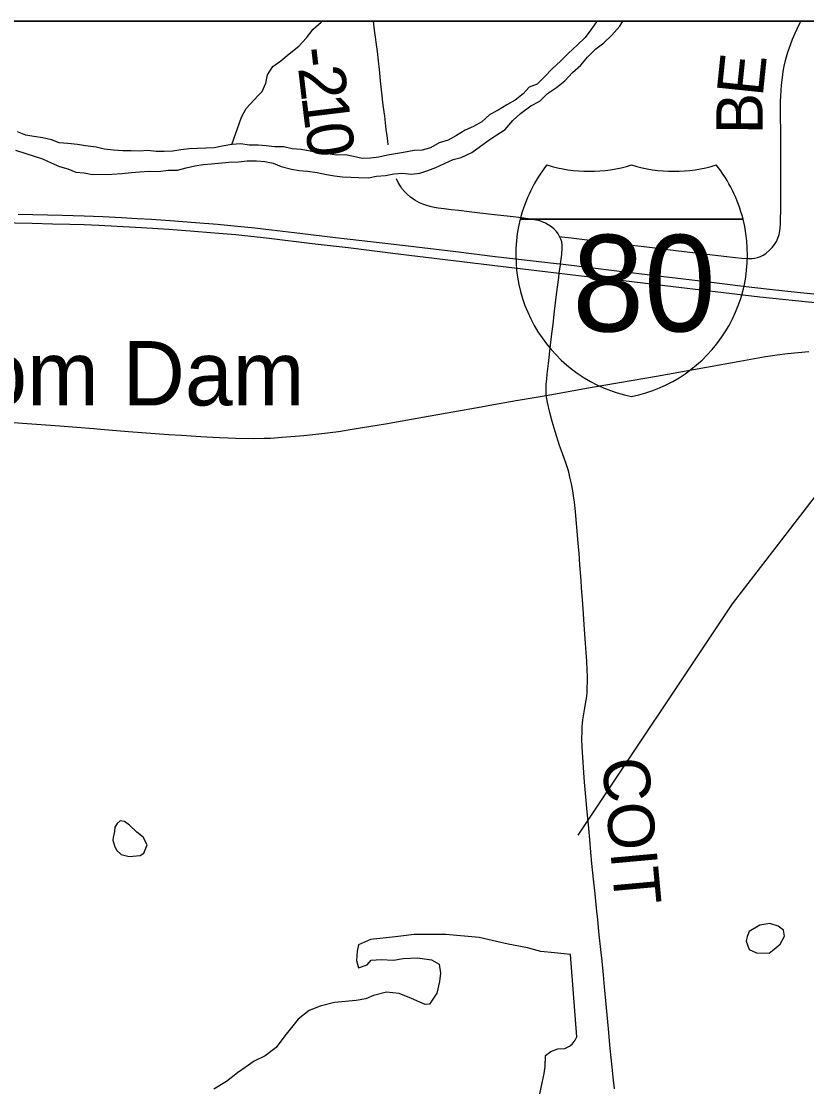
# Model space of a CAD drawing. Extents: x 0 to 34, y 0 to 22.
# Drawn here: x 6.131 to 7.094, y 19.311 to 20.617 of the extents above; entities that cross this region are included whole.
import ezdxf

# ---------------------------------------------------------------- set-up
doc = ezdxf.new("R2010")
doc.units = 0
for name, color, linetype in [('GM_X_Corporation', 7, 'Continuous'), ('GM_X_County_Road', 7, 'Continuous'), ('GM_X_County_Road_Text', 7, 'Continuous'), ('GM_X_Interstate_Location', 7, 'Continuous'), ('GM_X_Interstate_Route', 7, 'Continuous'), ('GM_X_Interstate_Shield', 7, 'Continuous'), ('GM_X_Major_River', 7, 'Continuous'), ('GM_X_Minor_Lake', 7, 'Continuous'), ('GM_X_Minor_River', 7, 'Continuous'), ('GM_X_State_Route', 7, 'Continuous'), ('GM_X_Township_Road', 7, 'Continuous'), ('GM_X_Township_Road_Text', 7, 'Continuous'), ('GM_X_Unincorporated_Text', 7, 'Continuous'), ('SH_Data', 7, 'Continuous')]:
    doc.layers.add(name, color=color, linetype=linetype)

msp = doc.modelspace()

# ---------------------------------------------------------------- linework, layer by layer
at = {"layer": 'GM_X_Corporation'}
msp.add_lwpolyline([(8.914, 20.6173), (5.0338, 20.6173)], dxfattribs=at)
at = {"layer": 'GM_X_County_Road'}
msp.add_lwpolyline([(6.8585, 19.3083), (6.8569, 19.3227), (6.8556, 19.335), (6.8532, 19.3578), (6.8511, 19.3817), (6.8463, 19.4334), (6.8449, 19.448), (6.8432, 19.4648), (6.8417, 19.4791), (6.8398, 19.4972), (6.838, 19.5154), (6.8365, 19.5297), (6.8346, 19.5474), (6.8328, 19.5654), (6.8309, 19.5844), (6.8295, 19.5984), (6.8281, 19.6142), (6.8265, 19.6322), (6.825, 19.6481), (6.8234, 19.6664), (6.8219, 19.6844), (6.8209, 19.696), (6.8196, 19.7149), (6.819, 19.7271), (6.8186, 19.7379), (6.8188, 19.7461), (6.819, 19.7529), (6.8193, 19.7561), (6.8198, 19.7609), (6.8204, 19.7655), (6.8222, 19.7755), (6.8238, 19.7847), (6.8244, 19.7894), (6.8249, 19.7948), (6.8251, 19.8002), (6.8253, 19.8071), (6.8252, 19.8143), (6.825, 19.8215), (6.8245, 19.8325), (6.8238, 19.8432), (6.823, 19.8547), (6.8214, 19.8771), (6.8205, 19.8906), (6.8193, 19.9083), (6.8182, 19.9225), (6.8175, 19.9318), (6.8161, 19.9508), (6.8151, 19.965), (6.8141, 19.9768), (6.8128, 19.9924), (6.8116, 20.0059), (6.8105, 20.0164), (6.8093, 20.0277), (6.8083, 20.0353), (6.8072, 20.0416), (6.8056, 20.0503), (6.8039, 20.0584), (6.8029, 20.0628), (6.8016, 20.0671), (6.7991, 20.0745), (6.7946, 20.0874), (6.7911, 20.0973), (6.7856, 20.1142), (6.7819, 20.1266), (6.7792, 20.1375), (6.7763, 20.1498), (6.7753, 20.1543), (6.7747, 20.1585)], dxfattribs=at)
at = {"layer": 'GM_X_Interstate_Route'}
for points in [[(6.1271, 20.3809), (6.1811, 20.3797), (6.2081, 20.3789), (6.231, 20.3779), (6.2536, 20.3768), (6.273, 20.3756), (6.2907, 20.3745), (6.3135, 20.373), (6.3446, 20.3706), (6.3715, 20.3684), (6.3959, 20.3661), (6.4174, 20.3639), (6.4376, 20.3616), (6.4726, 20.3576), (6.5164, 20.3523), (6.5304, 20.3507), (6.5487, 20.3486), (6.6055, 20.3418), (6.664, 20.335), (6.7123, 20.329), (6.7875, 20.3202), (6.7922, 20.3197), (6.8157, 20.317), (6.8613, 20.3115), (6.919, 20.3044), (6.9744, 20.2977), (6.994, 20.2953), (7.0165, 20.2926), (7.0487, 20.2888), (7.0827, 20.2852), (7.1151, 20.2817)], [(6.1022, 20.3705), (6.1443, 20.3698), (6.1693, 20.3691), (6.1905, 20.3685), (6.2081, 20.368), (6.2261, 20.3673), (6.2781, 20.3644), (6.3117, 20.3623), (6.338, 20.3602), (6.3677, 20.3579), (6.394, 20.3557), (6.4351, 20.3515), (6.4878, 20.3449), (6.5317, 20.3399), (6.5931, 20.3321), (6.7185, 20.3171), (6.7908, 20.3085), (6.8144, 20.3056), (6.8694, 20.2993), (6.9203, 20.2935), (7.0368, 20.2795), (7.1082, 20.2719)]]:
    msp.add_lwpolyline(points, dxfattribs=at)
at = {"layer": 'GM_X_Interstate_Shield'}
for p, q in [((6.7429, 20.3746), (7.0161, 20.3746)), ((7.0161, 20.3746), (6.7429, 20.3746)), ((7.0161, 20.3746), (6.7429, 20.3746))]:
    msp.add_line(p, q, dxfattribs=at)
for centre, start, end in [((6.915, 20.3311), 141.669, 165.8066), ((6.8276, 20.611), 253.0091, 286.9909), ((6.9314, 20.611), 253.0091, 286.9909), ((6.844, 20.3311), 14.1934, 38.331), ((6.915, 20.3311), 165.8066, 258.463), ((6.844, 20.3311), 281.537, 14.1934)]:
    msp.add_arc(centre, 0.1776, start, end, dxfattribs=at)
at = {"layer": 'GM_X_Major_River'}
for points in [[(6.8369, 20.6173), (6.8365, 20.6168), (6.8293, 20.6069), (6.8225, 20.5974), (6.8127, 20.5882), (6.8021, 20.5783), (6.7923, 20.5684), (6.7821, 20.5592), (6.7731, 20.5497), (6.7637, 20.5401), (6.7539, 20.5364), (6.7463, 20.5284)], [(6.774, 20.5265), (6.7762, 20.5288), (6.7872, 20.5361), (6.7974, 20.5441), (6.8068, 20.5544), (6.8174, 20.5636), (6.8253, 20.5731), (6.8355, 20.5834), (6.8453, 20.591), (6.8551, 20.6002), (6.8649, 20.6112), (6.8687, 20.6173)], [(6.1236, 20.4592), (6.135, 20.4556), (6.1467, 20.4519), (6.157, 20.4486), (6.1673, 20.4438), (6.1776, 20.4394), (6.1878, 20.4364), (6.1977, 20.4324), (6.2079, 20.4313), (6.2178, 20.4296), (6.242, 20.4298), (6.2545, 20.4308), (6.2659, 20.432), (6.2757, 20.4325), (6.2878, 20.4334), (6.2992, 20.4332), (6.3109, 20.4348), (6.3223, 20.4346), (6.3329, 20.4377), (6.3438, 20.4402), (6.354, 20.4418), (6.3642, 20.4427), (6.3854, 20.4444), (6.3972, 20.445), (6.4081, 20.4462), (6.4195, 20.446), (6.4294, 20.4453), (6.4396, 20.4432), (6.4495, 20.4391), (6.4624, 20.4358), (6.4719, 20.4344), (6.4818, 20.4334), (6.4939, 20.432), (6.5053, 20.4295), (6.5152, 20.4277), (6.525, 20.4267), (6.5349, 20.4261), (6.5447, 20.4258), (6.5568, 20.4252), (6.5667, 20.4272), (6.5776, 20.4281), (6.5878, 20.4301), (6.5984, 20.431), (6.6094, 20.43), (6.6196, 20.4312), (6.6295, 20.4344), (6.6393, 20.4379), (6.6498, 20.443), (6.6607, 20.448), (6.6706, 20.4504), (6.6834, 20.4566), (6.6943, 20.464), (6.7044, 20.4717), (6.7142, 20.4779), (6.7243, 20.4848), (6.7337, 20.4956), (6.7434, 20.5044), (6.7558, 20.5137), (6.7671, 20.5195), (6.774, 20.5265)], [(6.7463, 20.5284), (6.7366, 20.5207), (6.7264, 20.515), (6.7158, 20.5084), (6.7057, 20.503), (6.6959, 20.4939), (6.6857, 20.4881), (6.6755, 20.4838), (6.6646, 20.4773), (6.6544, 20.4715), (6.6435, 20.4681), (6.6329, 20.4623), (6.6227, 20.4592), (6.6129, 20.4587), (6.5997, 20.4563), (6.5898, 20.4547), (6.58, 20.4532), (6.5694, 20.4508), (6.5592, 20.4496), (6.549, 20.4491), (6.5384, 20.4513), (6.5285, 20.4535), (6.5175, 20.4531), (6.5069, 20.4549), (6.4956, 20.4559), (6.4853, 20.4581), (6.4743, 20.4599), (6.463, 20.461), (6.4527, 20.4632), (6.4418, 20.4635), (6.4312, 20.4645), (6.4213, 20.4652), (6.4103, 20.4655), (6.4001, 20.467), (6.3891, 20.4661), (6.3774, 20.4641), (6.3676, 20.4622), (6.3369, 20.4608), (6.3267, 20.4596), (6.3169, 20.458), (6.3059, 20.4575), (6.2961, 20.4578), (6.2862, 20.4589), (6.276, 20.458), (6.2658, 20.4583), (6.2556, 20.4583), (6.2438, 20.4593), (6.2325, 20.4604), (6.2226, 20.4629), (6.2094, 20.4644), (6.1999, 20.4662), (6.1881, 20.4676), (6.1775, 20.4683), (6.1677, 20.472), (6.1571, 20.4742), (6.1464, 20.476), (6.1366, 20.4775), (6.1263, 20.4819)]]:
    msp.add_lwpolyline(points, dxfattribs=at)
at = {"layer": 'GM_X_Minor_Lake'}
for p, q in [((6.245, 19.6237), (6.2434, 19.6163)), ((7.0369, 19.5088), (7.0237, 19.5011)), ((6.8124, 19.372), (6.8044, 19.4732))]:
    msp.add_line(p, q, dxfattribs=at)
for points in [[(6.2434, 19.6163), (6.2432, 19.6131), (6.2451, 19.6063), (6.2478, 19.601), (6.2535, 19.5957), (6.263, 19.5931), (6.2766, 19.5944), (6.2811, 19.5971), (6.2852, 19.6073), (6.2802, 19.6168), (6.2726, 19.6232), (6.2635, 19.6318), (6.2574, 19.6359), (6.2521, 19.637), (6.2483, 19.6336), (6.2457, 19.629), (6.245, 19.6237)], [(7.0237, 19.5011), (7.0211, 19.495), (7.02, 19.4893), (7.0235, 19.4791), (7.0326, 19.475), (7.0481, 19.4747), (7.0542, 19.4797), (7.0617, 19.4858), (7.0669, 19.4953), (7.0657, 19.5029), (7.0592, 19.5078), (7.049, 19.5111), (7.0369, 19.5088)], [(6.8044, 19.4732), (6.7968, 19.4739), (6.7851, 19.475), (6.768, 19.4767), (6.7517, 19.4812), (6.7282, 19.4855), (6.7138, 19.4888), (6.6926, 19.494), (6.6517, 19.4975), (6.6127, 19.4976), (6.59, 19.4947), (6.5594, 19.4915), (6.5443, 19.4849), (6.5428, 19.4773), (6.5422, 19.4655), (6.5445, 19.4568), (6.5551, 19.4603), (6.56, 19.466), (6.5721, 19.4669), (6.5876, 19.4659), (6.5993, 19.4682), (6.6167, 19.4688), (6.6341, 19.4666), (6.6433, 19.461), (6.6449, 19.45), (6.6438, 19.4401), (6.6405, 19.4257), (6.6315, 19.412), (6.6262, 19.4116), (6.6095, 19.419), (6.5943, 19.4253), (6.5788, 19.4267), (6.5629, 19.4228), (6.5535, 19.4186), (6.5418, 19.4166), (6.5149, 19.4141), (6.4976, 19.4098), (6.484, 19.4044), (6.4704, 19.3937), (6.4543, 19.3734), (6.4434, 19.3589), (6.4299, 19.3486), (6.4163, 19.3424), (6.4054, 19.3344), (6.396, 19.3279), (6.3825, 19.3171), (6.367, 19.3079)], [(6.7664, 19.3003), (6.7697, 19.3155), (6.7722, 19.3269), (6.7733, 19.3357), (6.7739, 19.349), (6.7803, 19.3539), (6.789, 19.3574), (6.7977, 19.3579), (6.8034, 19.3606), (6.8064, 19.3632), (6.8101, 19.3678), (6.8124, 19.372)]]:
    msp.add_lwpolyline(points, dxfattribs=at)
at = {"layer": 'GM_X_Minor_River'}
for p, q in [((7.2112, 20.1735), (7.0028, 19.903)), ((7.0028, 19.903), (6.8135, 19.6193))]:
    msp.add_line(p, q, dxfattribs=at)
for points in [[(6.4216, 20.5262), (6.4263, 20.5312), (6.4308, 20.5415), (6.4327, 20.5518), (6.4395, 20.5617), (6.4493, 20.5689), (6.4595, 20.5773), (6.4712, 20.5869), (6.4806, 20.5972), (6.4889, 20.6078), (6.4987, 20.6162), (6.4997, 20.6173)], [(6.3891, 20.4661), (6.401, 20.4996), (6.4066, 20.5104), (6.4216, 20.5262)]]:
    msp.add_lwpolyline(points, dxfattribs=at)
at = {"layer": 'GM_X_State_Route'}
for points in [[(6.6948, 20.1445), (6.7055, 20.1464), (6.738, 20.1522), (6.7747, 20.1585), (6.831, 20.1685), (6.91, 20.1823), (7.0121, 20.2005), (7.0438, 20.2062), (7.058, 20.2085), (7.0709, 20.2101), (7.0839, 20.2113), (7.097, 20.2122)], [(6.228, 20.1172), (6.2623, 20.1143), (6.3115, 20.1107), (6.3275, 20.1097), (6.351, 20.1083), (6.3659, 20.1075), (6.374, 20.107), (6.3845, 20.1066), (6.3938, 20.1063), (6.4156, 20.1059), (6.4286, 20.106), (6.4366, 20.1063), (6.4509, 20.1073), (6.4774, 20.1096), (6.4997, 20.1118), (6.52, 20.1144), (6.539, 20.1174), (6.5776, 20.1239), (6.6254, 20.1322), (6.6948, 20.1445)], [(6.0887, 20.1276), (6.1323, 20.1244), (6.1554, 20.1228), (6.1781, 20.1212), (6.2199, 20.1179), (6.228, 20.1172)]]:
    msp.add_lwpolyline(points, dxfattribs=at)
at = {"layer": 'GM_X_Township_Road'}
for points in [[(6.581, 20.4658), (6.5803, 20.4706), (6.5795, 20.4769), (6.5786, 20.4845), (6.5766, 20.5011), (6.5749, 20.5146), (6.5733, 20.5294), (6.5716, 20.5442), (6.5701, 20.5582), (6.569, 20.5687), (6.5677, 20.5801), (6.5642, 20.6064), (6.5628, 20.6173)], [(6.7912, 20.3536), (6.794, 20.3532), (6.8055, 20.3518), (6.8282, 20.349), (6.842, 20.3473), (6.8718, 20.3437), (6.8947, 20.341), (6.908, 20.3394), (6.9369, 20.3359), (6.9755, 20.3313), (6.9927, 20.3292), (7.0071, 20.3275), (7.0147, 20.3268), (7.0213, 20.3264), (7.0272, 20.3266), (7.0304, 20.327), (7.034, 20.3278), (7.0374, 20.329), (7.0409, 20.3307), (7.0441, 20.3327), (7.0488, 20.3365), (7.052, 20.3399), (7.0548, 20.3436), (7.0571, 20.3474), (7.059, 20.3515), (7.0604, 20.3559), (7.0612, 20.3602), (7.0617, 20.3639), (7.062, 20.3688), (7.0622, 20.3745), (7.0624, 20.3856), (7.0626, 20.4013), (7.0626, 20.4156), (7.0626, 20.4258), (7.0626, 20.4502), (7.0625, 20.4745), (7.0621, 20.5087), (7.0622, 20.5191), (7.0626, 20.526), (7.0635, 20.5391), (7.0644, 20.5485), (7.0653, 20.5556), (7.0666, 20.5624), (7.0686, 20.5707), (7.0712, 20.5795), (7.0743, 20.5884), (7.077, 20.5953), (7.0801, 20.6029), (7.0825, 20.6082), (7.0862, 20.6159), (7.0869, 20.6173)], [(6.7912, 20.3536), (6.7895, 20.3565), (6.7873, 20.3595), (6.7847, 20.3622), (6.7813, 20.3653), (6.7773, 20.3679), (6.774, 20.3697), (6.7709, 20.3711), (6.7668, 20.3726), (6.7627, 20.3736), (6.7576, 20.3744), (6.745, 20.3761), (6.7306, 20.3779), (6.7115, 20.3801), (6.6935, 20.3822), (6.6801, 20.3838), (6.6677, 20.3852), (6.6582, 20.3862), (6.6495, 20.3873), (6.6422, 20.3882), (6.6373, 20.3891), (6.6324, 20.3902), (6.6271, 20.3918), (6.6234, 20.3932), (6.6194, 20.3948), (6.6135, 20.3981), (6.6084, 20.4016), (6.6041, 20.4052), (6.6008, 20.4086), (6.5978, 20.4123), (6.5958, 20.4152), (6.593, 20.4198), (6.5909, 20.4241)], [(6.7747, 20.1585), (6.7745, 20.1645), (6.7745, 20.1685), (6.7747, 20.172), (6.7754, 20.1787), (6.7761, 20.1846), (6.7776, 20.1978), (6.7802, 20.2201), (6.7818, 20.2339), (6.7831, 20.2459), (6.7851, 20.2618), (6.7875, 20.2823), (6.7901, 20.303), (6.7908, 20.3085), (6.7921, 20.3187), (6.7922, 20.3197), (6.7937, 20.3314), (6.7944, 20.3393), (6.7943, 20.3432), (6.7938, 20.3468), (6.7928, 20.35), (6.7912, 20.3536)]]:
    msp.add_lwpolyline(points, dxfattribs=at)
at = {"layer": 'SH_Data'}
msp.add_line((2.114, 20.6173), (8.914, 20.6173), dxfattribs=at)

# ---------------------------------------------------------------- texts
at = {"layer": 'GM_X_County_Road_Text'}
for s, rotation, p in [('COIT', 275.2175, (6.8431, 19.7121)), ('INFIRMARY', 69.1728, (7.0842, 19.1066))]:
    msp.add_text(s, height=0.05682, rotation=rotation, dxfattribs=at).set_placement(p)
at = {"layer": 'GM_X_Interstate_Location'}
for s in ['-', '.', ',']:
    msp.add_text(s, height=0.000189, dxfattribs=at).set_placement((6.8795, 20.2991))
msp.add_text('80', height=0.000189, rotation=0, dxfattribs=at).set_placement((6.8408, 20.2599))
at = {"layer": 'GM_X_Interstate_Shield'}
msp.add_text('80', height=0.11837, dxfattribs=at).set_placement((6.8067, 20.237))
at = {"layer": 'GM_X_Township_Road_Text'}
for s, rotation, p in [('-', 276.5622, (6.4677, 20.5835)), ('E', 84.0839, (7.0402, 20.5239)), ('2', 276.6648, (6.4703, 20.5602)), ('1', 276.9817, (6.4744, 20.5251)), ('B', 89.7151, (7.0401, 20.4787)), ('0', 277.9366, (6.4788, 20.4894))]:
    msp.add_text(s, height=0.0568, rotation=rotation, dxfattribs=at).set_placement(p)
at = {"layer": 'GM_X_Unincorporated_Text'}
msp.add_text('Freedom Dam', height=0.078977, rotation=0, dxfattribs=at).set_placement((5.8033, 20.1462))

doc.saveas('drawing.dxf')
